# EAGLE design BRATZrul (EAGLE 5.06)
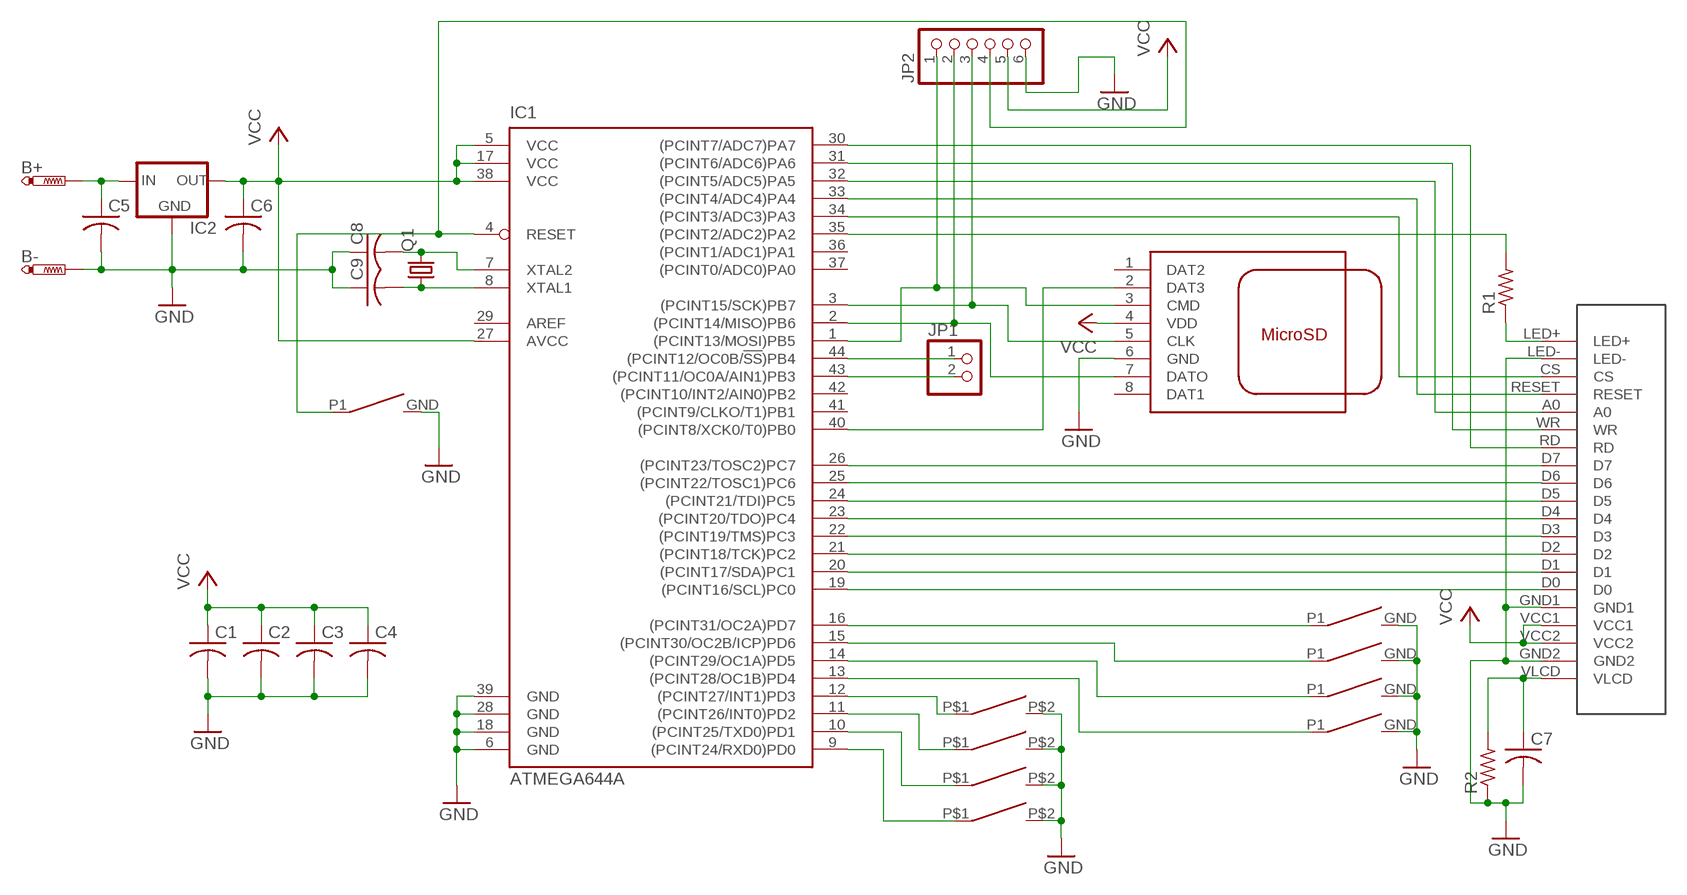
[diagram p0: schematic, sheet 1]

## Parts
B+  PTR1PAD1-13Y  [P1-13Y]
B-  PTR1PAD1-13Y  [P1-13Y]
C1  C-USC0805  [C0805]
C2  C-USC0805  [C0805]
C3  C-USC0805  [C0805]
C4  C-USC0805  [C0805]
C5  C-USC0805  [C0805]
C6  C-USC0805  [C0805]
C7  C-USC0805  [C0805]
C8  C-USC0805  [C0805]
C9  C-USC0805  [C0805]
IC1  ATMEGA644A  [TQFP44]
IC2  XC63FPP  [SOT89R]
JP1  PINHD-1X2  [1X02]
JP2  PINHD-1X6  [1X06]
LCD1  DISPLAY_WOOLWORTH1  [DISPLAYWOOL2]
MIUCHIZ_CURSOR1  MIUCHIZ_CURSOR  [MIUCHIZ_CURSER]
MIUCHIZ_CURSOR2  MIUCHIZ_CURSOR  [MIUCHIZ_CURSER]
MIUCHIZ_CURSOR3  MIUCHIZ_CURSOR  [MIUCHIZ_CURSER]
MIUCHIZ_CURSOR4  MIUCHIZ_CURSOR  [MIUCHIZ_CURSER]
MIUCHIZ_TASTER1  MIUCHIZ_TASTER  [MIUCHIZ_TASTER]
MIUCHIZ_TASTER2  MIUCHIZ_TASTER  [MIUCHIZ_TASTER]
MIUCHIZ_TASTER3  MIUCHIZ_TASTER  [MIUCHIZ_TASTER]
MIUCHIZ_TASTER4  MIUCHIZ_TASTER  [MIUCHIZ_TASTER]
MIUCHIZ_TASTER5  MIUCHIZ_TASTER  [MIUCHIZ_TASTER]
Q1  CRYSTALHC49UP  [HC49UP]
R1  R-US_R0805  [R0805]
R2  R-US_R0805  [R0805]
U$1  112A-TAA0-R01  [112A-TAA0-R01]

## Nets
GND: B-.1(TP) C1.2 C2.2 C3.2 C4.2 C5.2 C6.2 C7.2 C8.1 C9.1 IC1.6(GND) IC1.18(GND) IC1.28(GND) IC1.39(GND) IC2.1(GND) JP2.6 LCD1.GND1 LCD1.GND2 LCD1.LED- MIUCHIZ_CURSOR1.P$2(GND) MIUCHIZ_CURSOR2.P$2(GND) MIUCHIZ_CURSOR3.P$2(GND) MIUCHIZ_CURSOR4.P$2(GND) MIUCHIZ_TASTER1.GND MIUCHIZ_TASTER2.GND MIUCHIZ_TASTER3.GND MIUCHIZ_TASTER4.GND MIUCHIZ_TASTER5.GND R2.1 U$1.6(GND)
N$1: IC1.19((PCINT16/SCL)PC0) LCD1.D0
N$2: IC1.20((PCINT17/SDA)PC1) LCD1.D1
N$3: IC1.21((PCINT18/TCK)PC2) LCD1.D2
N$4: IC1.22((PCINT19/TMS)PC3) LCD1.D3
N$5: IC1.23((PCINT20/TDO)PC4) LCD1.D4
N$6: IC1.24((PCINT21/TDI)PC5) LCD1.D5
N$7: IC1.25((PCINT22/TOSC1)PC6) LCD1.D6
N$8: IC1.26((PCINT23/TOSC2)PC7) LCD1.D7
N$11: IC1.30((PCINT7/ADC7)PA7) LCD1.RD
N$12: IC1.31((PCINT6/ADC6)PA6) LCD1.WR
N$13: IC1.32((PCINT5/ADC5)PA5) LCD1.A0
N$14: IC1.33((PCINT4/ADC4)PA4) LCD1.RESET
N$15: IC1.34((PCINT3/ADC3)PA3) LCD1.CS
N$16: IC1.35((PCINT2/ADC2)PA2) R1.2
N$17: LCD1.LED+ R1.1
N$18: IC1.43((PCINT11/OC0A/AIN1)PB3) JP1.2
N$19: IC1.44((PCINT12/OC0B/!SS!)PB4) JP1.1
N$20: C8.2 IC1.7(XTAL2) Q1.2
N$21: C9.2 IC1.8(XTAL1) Q1.1
N$22: IC1.16((PCINT31/OC2A)PD7) MIUCHIZ_TASTER2.P1
N$23: IC1.15((PCINT30/OC2B/ICP)PD6) MIUCHIZ_TASTER1.P1
N$24: IC1.14((PCINT29/OC1A)PD5) MIUCHIZ_TASTER3.P1
N$25: IC1.13((PCINT28/OC1B)PD4) MIUCHIZ_TASTER4.P1
N$26: IC1.12((PCINT27/INT1)PD3) MIUCHIZ_CURSOR1.P$1(P1)
N$27: IC1.11((PCINT26/INT0)PD2) MIUCHIZ_CURSOR2.P$1(P1)
N$28: IC1.10((PCINT25/TXD0)PD1) MIUCHIZ_CURSOR3.P$1(P1)
N$29: IC1.9((PCINT24/RXD0)PD0) MIUCHIZ_CURSOR4.P$1(P1)
N$30: IC1.3((PCINT15/SCK)PB7) JP2.3 U$1.5(CLK)
N$31: IC1.2((PCINT14/MISO)PB6) JP2.2 U$1.7(DATO)
N$32: IC1.1((PCINT13/MOSI)PB5) JP2.1 U$1.3(CMD)
N$33: IC1.40((PCINT8/XCK0/T0)PB0) U$1.2(DAT3)
N$34: B+.1(TP) C5.1 IC2.2(IN)
N$36: IC1.4(RESET) JP2.4 MIUCHIZ_TASTER5.P1
N$37: C7.1 LCD1.VLCD R2.2
VCC: C1.1 C2.1 C3.1 C4.1 C6.1 IC1.5(VCC) IC1.17(VCC) IC1.27(AVCC) IC1.38(VCC) IC2.3(OUT) JP2.5 LCD1.VCC1 LCD1.VCC2 U$1.4(VDD)
Unconnected: IC1.29(AREF) IC1.36((PCINT1/ADC1)PA1) IC1.37((PCINT0/ADC0)PA0) IC1.41((PCINT9/CLKO/T1)PB1) IC1.42((PCINT10/INT2/AIN0)PB2) U$1.1(DAT2) U$1.8(DAT1)

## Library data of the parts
B+ B- = testpad:PTR1: TEST PIN
C1-C9 = rcl:C-US: CAPACITOR, American symbol
IC1 = atmel:ATMEGA644: 8-bit Microcontroller with 64K Bytes In-System Programmable Flash Source: http://www.atmel.com/dyn/resources/prod_documents/doc2593.pdf
IC2 = v-reg:XC63FP: Positiv Voltage Regulators www.torex.co.jp/english/product/pro02/pdf/0201_xc62fp.pdf
JP1 = pinhead:PINHD-1X2: PIN HEADER
JP2 = pinhead:PINHD-1X6: PIN HEADER
LCD1 = Display_woolworthv2:DISPLAY_WOOLWORTH1
MIUCHIZ_CURSOR1-MIUCHIZ_CURSOR4 = Miuchiz_Taster:MIUCHIZ_CURSOR
MIUCHIZ_TASTER1-MIUCHIZ_TASTER5 = Miuchiz_Taster:MIUCHIZ_TASTER
Q1 = crystal:CRYSTAL: CRYSTAL
R1 R2 = rcl:R-US_: RESISTOR, American symbol
U$1 = con-memcard:112A-TAA0-R01: MicroSD Card Slot Part No.: MICROSD Available at IT-WNS Datasheet : http://www.it-wns.de/data/datenblatt_0000032_1.pdf

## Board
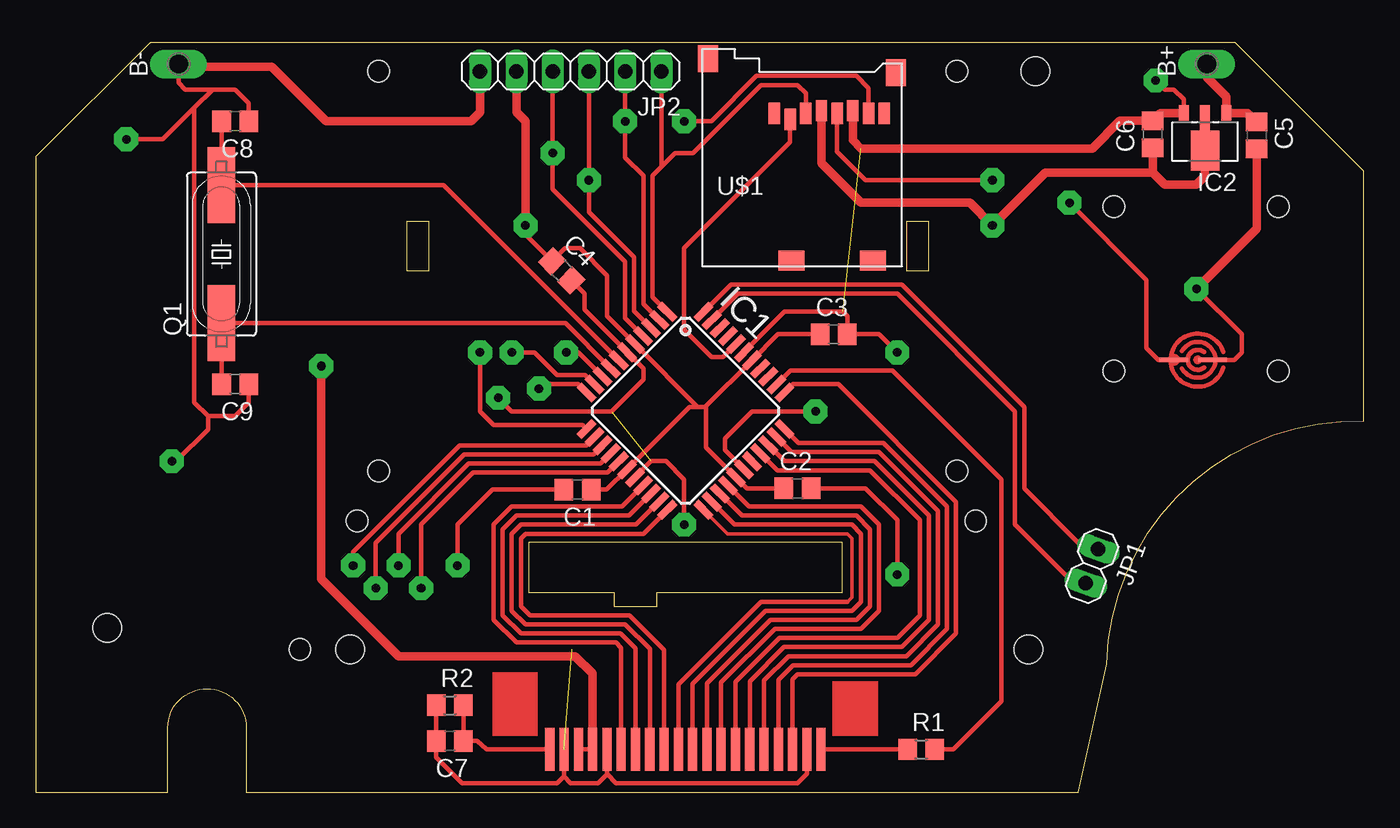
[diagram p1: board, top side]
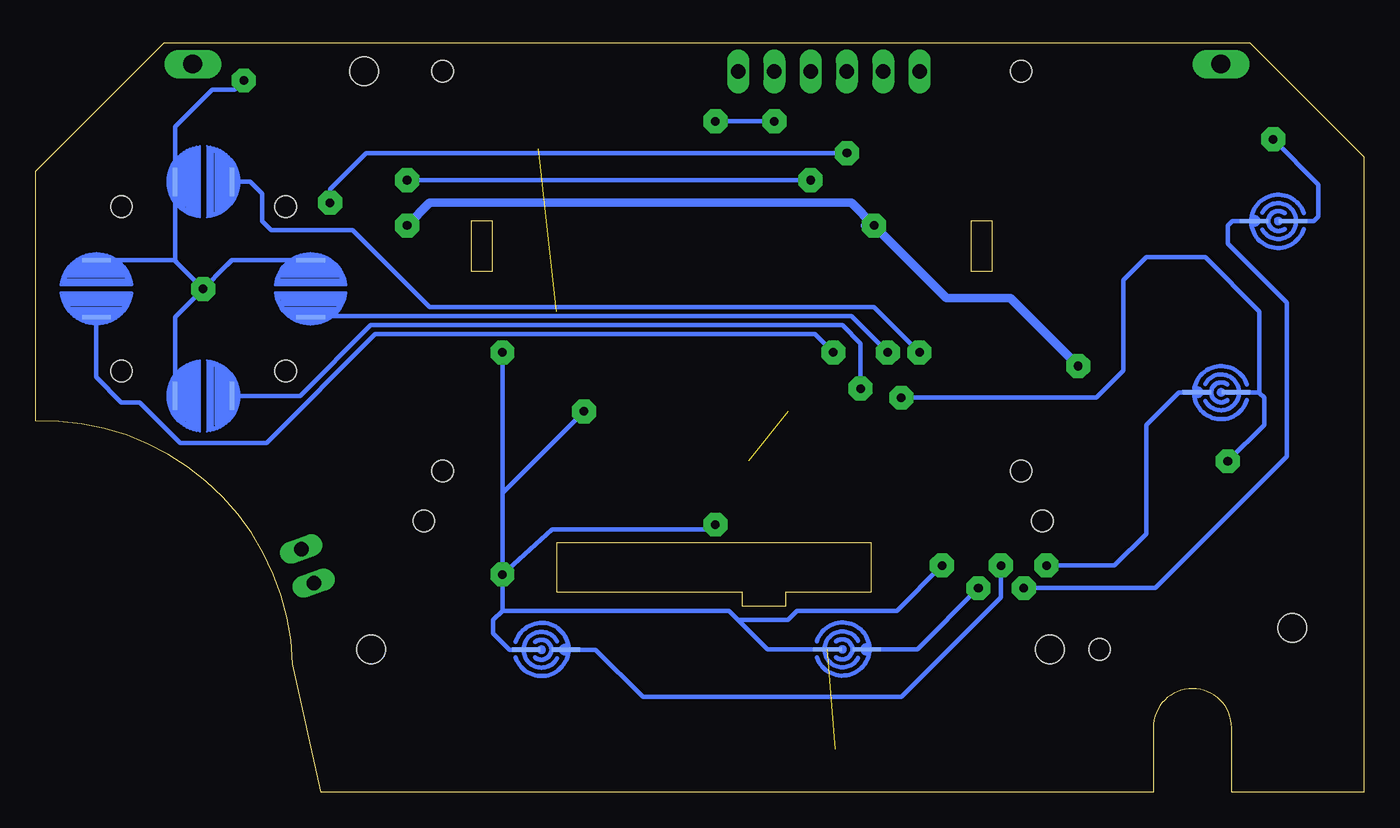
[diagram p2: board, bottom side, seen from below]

Size 93 x 52.5 mm. Coordinates in mm from the lower left corner, seen from the top.
Outline: 0,0 9.25,0 9.25,4.5 arc-180 14.75,4.5 14.75,0 73,0 75,9 arc-90 93,26 93,43.5 84,52.5 8,52.5 0,44.5 0,0
Outline: 34.5,14 40.5,14 40.5,13 43.5,13 43.5,14 56.5,14 56.5,17.5 34.5,17.5 34.5,14
Outline: 26,36.5 26,40 27.5,40 27.5,36.5 26,36.5
Outline: 61,36.5 61,40 62.5,40 62.5,36.5 61,36.5
Copper layers (1*16): Top 0.035mm / dielectric 1.5mm / Bottom 0.035mm
Design rules "default *": minimum track width 10mil, minimum drill 24mil, track to track 8mil, track to pad 8mil, pad to pad 8mil, via to via 8mil, smd to smd 8mil, copper to edge 10mil, drill to drill 8mil, minimum pad ring 10mil, minimum via ring 8mil, stop-mask expansion 4mil, vias tented up to drill 0mil, thermal gap 10mil
Holes 2 mm at 5,11.5 22,10 69.5,10 70,50.5
Holes 1.5 mm at 24,22.5 24,50.5 87,29.5 75.5,29.5 75.5,41 87,41 18.5,10 22.5,19 65.82,19 64.5,50.5 64.5,22.5

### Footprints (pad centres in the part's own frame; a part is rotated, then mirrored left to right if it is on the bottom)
P1-13Y = drill 1.321 pad 1.905 long: 1 0,0
C0805 = smd 1.3 x 1.5: 1 -0.95,0; 2 0.95,0
TQFP44 = smd 1.5 x 0.5: 1 -5.8,4; 2 -5.8,3.2; 3 -5.8,2.4; 4 -5.8,1.6; 5 -5.8,0.8; 6 -5.8,0; 7 -5.8,-0.8; 8 -5.8,-1.6; 9 -5.8,-2.4; 10 -5.8,-3.2; 11 -5.8,-4; 23 5.8,-4; 24 5.8,-3.2; 25 5.8,-2.4; 26 5.8,-1.6; 27 5.8,-0.8; 28 5.8,0; 29 5.8,0.8; 30 5.8,1.6; 31 5.8,2.4; 32 5.8,3.2; 33 5.8,4 | smd 0.5 x 1.5: 12 -4,-5.8; 13 -3.2,-5.8; 14 -2.4,-5.8; 15 -1.6,-5.8; 16 -0.8,-5.8; 17 0,-5.8; 18 0.8,-5.8; 19 1.6,-5.8; 20 2.4,-5.8; 21 3.2,-5.8; 22 4,-5.8; 34 4,5.8; 35 3.2,5.8; 36 2.4,5.8; 37 1.6,5.8; 38 0.8,5.8; 39 0,5.8; 40 -0.8,5.8; 41 -1.6,5.8; 42 -2.4,5.8; 43 -3.2,5.8; 44 -4,5.8
SOT89R = smd 0.7 x 1.1: 1 1.5,-1.75; 2 -1.5,-1.75 | smd 0.7 x 1.8: 3 0,-1.4 | smd 2 x 2.8: 4 0,0.9
1X02 = drill 1.016 long: 1 -1.27,0; 2 1.27,0
1X06 = drill 1.016 long: 1 -6.35,0; 2 -3.81,0; 3 -1.27,0; 4 1.27,0; 5 3.81,0; 6 6.35,0
DISPLAYWOOL2 = smd 3 x 0.635: A0 0,-4; CS 0,-2; D0 0,-14; D1 0,-13; D2 0,-12; D3 0,-11; D4 0,-10; D5 0,-9; D6 0,-8; D7 0,-7; GND1 0,-15; GND2 0,-18; LED+ 0,0; LED- 0,-1; RD 0,-6; RESET 0,-3; VCC1 0,-16; VCC2 0,-17; VLCD 0,-19; WR 0,-5
MIUCHIZ_CURSER = smd 2 x 0.3: P$1 0,-2; P$2 0,2
MIUCHIZ_TASTER = smd 2 x 0.3: GND 1.059,0; P1 -1.691,0
HC49UP = smd 5.334 x 1.93: 1 -4.826,0; 2 4.826,0
R0805 = smd 1.3 x 1.5: 1 -0.95,0; 2 0.95,0
112A-TAA0-R01 = smd 0.8 x 1.5: 1 5.05,10.7; 2 6.15,10.3; 3 7.25,10.7; 4 8.35,10.9; 5 9.45,10.7; 6 10.55,10.9; 7 11.65,10.7; 8 12.75,10.7 | smd 1.4 x 1.9: 9 0.4,14.55; 9@2 13.55,13.55 | smd 1.8 x 1.4: 10 6.25,0.4; 10@2 11.95,0.4

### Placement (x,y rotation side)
B+  82,51 90 top
B-  10,51 90 top
C1  37.94,21.19 180 top
C2  53.34,21.27 0 top
C3  55.88,32.07 0 top
C4  36.83,36.51 315 top
C5  85.5,46 270 top
C6  78.21,46.08 90 top
C7  29,3.59 180 top
C8  13.97,46.99 180 top
C9  13.97,28.57 180 top
IC1  45.5,26.71 315 top
IC2  81.88,45.82 180 top
JP1  73.97,15.83 250 top
JP2  37.47,50.48 180 top
LCD1  55,3 270 top
MIUCHIZ_CURSOR1  81.25,42.75 90 bottom
MIUCHIZ_CURSOR2  81.25,27.75 90 bottom
MIUCHIZ_CURSOR3  73.75,35.25 0 bottom
MIUCHIZ_CURSOR4  88.75,35.25 0 bottom
MIUCHIZ_TASTER1  57.58,9.97 180 bottom
MIUCHIZ_TASTER2  36.5,10 180 bottom
MIUCHIZ_TASTER3  6,40 0 bottom
MIUCHIZ_TASTER4  10,28 0 bottom
MIUCHIZ_TASTER5  81.36,30.28 0 top
Q1  13.01,37.68 90 top
R1  62,3 0 top
R2  29,6.09 0 top
U$1  46.67,36.83 0 top

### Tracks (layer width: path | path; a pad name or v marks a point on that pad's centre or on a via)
GND  (via drill 0.6 pad 1.68)  (3 unrouted)
  Top 0.305: IC1.18 43.1,23.18 44.13,23.18 45.4,21.91 v45.4,18.73 | C1.2 31.99,21.19 29.53,18.73 v29.53,15.88 | v60.33,15.24 60.33,19.05 58.1,21.27 C2.2 | IC1.28 48.26,23.95 48.26,24.77 50.16,26.67 v54.61,26.67 | R2.1 C7.2 28.05,2.43 29.84,0.64 36.51,0.64 37,1.12 LCD1.GND2 37,1.1 37.47,0.64 39.37,0.64 40,1.26 LCD1.GND1 40.01,1.27 40.64,0.64 53.34,0.64 54,1.29 LCD1.LED- | IC1.39 52.45,33.66 56.52,33.66 56.83,33.34 C3.2 59.05,32.07 v60.33,30.8 | B-.1 10,49.69 10.48,49.21 12.38,49.21 | 12.38,49.21 13.97,49.21 14.92,48.26 C8.1 | C9.1 14.92,27.3 13.97,26.35 12.06,26.35 | 12.06,26.35 11.11,27.3 11.11,47.94 | 11.11,47.94 12.38,49.21 | C4.2 38.42,34.92 38.42,33.79 IC1.6 42.55,29.66 42.55,28.89 40.32,26.67 33.34,26.67 v32.38,27.62 | C4.2 | 11.11,47.94 8.89,45.72 v6.35,45.72 | v9.53,23.18 9.84,23.18 12.06,25.4 12.06,26.35 | v78.42,49.85 79.06,49.21 79.69,49.21 80.38,48.52 IC2.1 | MIUCHIZ_TASTER5.GND 83.94,30.28 84.45,30.8 84.45,32.07 v81.28,35.24
  Top 0.61: IC2.1 78.75,47.57 C6.2 75.92,47.02 73.98,45.09 57.78,45.09 57.22,45.65 U$1.6 | JP2.6 31.11,47.62 30.48,46.99 20.32,46.99 16.51,50.8 10.2,50.8 B-.1 | C5.2 85.5,39.46 v81.28,35.24
  Bottom 0.305: 80.96,35.56 80.01,36.51 | 80.01,36.51 79.25,37.27 | MIUCHIZ_CURSOR4.P$2 83.29,37.25 83.03,36.99 | 83.03,36.99 v81.28,35.24 83.25,33.27 MIUCHIZ_CURSOR2.P$2 | MIUCHIZ_CURSOR3.P$2 79.27,37.25 80.01,36.51 | 83.03,36.99 83.25,37.21 MIUCHIZ_CURSOR1.P$2 83.25,46.61 80.64,49.21 79.06,49.21 v78.42,49.85 | MIUCHIZ_TASTER1.GND 59.82,9.97 60.96,11.11 60.96,12.06 60.33,12.7 | 60.33,12.7 44.45,12.7 43.81,12.06 | 43.81,12.06 40.32,12.06 39.69,12.7 32.7,12.7 v29.53,15.88 | MIUCHIZ_TASTER2.GND 41.75,10 43.81,12.06 | v45.4,18.73 45.72,18.41 56.83,18.41 v60.33,15.24 | 60.33,12.7 v60.33,15.24 | 60.33,20.95 v54.61,26.67 | v60.33,15.24 60.33,20.95 | 60.33,20.95 v60.33,30.8 | v6.35,45.72 3.17,42.55 3.17,40.32 3.5,40 MIUCHIZ_TASTER3.GND | MIUCHIZ_TASTER4.GND 7.36,28 7.3,27.94 | 7.3,27.94 6.99,27.62 6.99,25.72 v9.53,23.18 | v32.38,27.62 18.73,27.62 16.83,29.53 16.83,35.88 15.24,37.47 11.11,37.47 7.3,33.66 7.3,27.94
  Bottom 0.61: v81.28,35.24 80.96,35.56
N$1
  Top 0.305: LCD1.D0 41,10.12 40.64,10.48 33.66,10.48 32.07,12.06 32.07,18.73 33.34,20 41.06,20 IC1.19
N$2
  Top 0.305: LCD1.D1 42,10.07 40.96,11.11 33.97,11.11 32.7,12.38 32.7,18.41 33.66,19.37 41.55,19.37 IC1.20
N$3
  Top 0.305: IC1.21 42.05,18.73 33.97,18.73 33.34,18.1 33.34,12.7 34.29,11.75 41.27,11.75 43,10.02 LCD1.D2
N$4
  Top 0.305: IC1.22 42.55,18.1 34.29,18.1 33.97,17.78 33.97,13.02 34.61,12.38 41.59,12.38 44,9.97 LCD1.D3
N$5
  Top 0.254: IC1.23 48.45,18.1 56.83,18.1 57.15,17.78 57.15,13.65 56.83,13.34
  Top 0.305: LCD1.D4 45,7.54 50.8,13.34 56.83,13.34
N$6
  Top 0.305: IC1.24 48.95,18.73 57.15,18.73 57.78,18.1 57.78,13.34 57.15,12.7 51.12,12.7 46,7.58 LCD1.D5
N$7
  Top 0.305: IC1.25 49.45,19.37 57.47,19.37 58.42,18.41 58.42,13.02 57.47,12.06 51.44,12.06 47,7.63 LCD1.D6
N$8
  Top 0.305: IC1.26 49.94,20 57.78,20 59.05,18.73 59.05,12.7 57.78,11.43 51.75,11.43 48,7.68 LCD1.D7
N$11
  Top 0.305: IC1.30 51.93,22.54 58.42,22.54 61.91,19.05 61.91,12.38 60.33,10.79 52.07,10.79 49,7.72 LCD1.RD
N$12
  Top 0.305: IC1.31 52.42,23.18 58.74,23.18 62.55,19.37 62.55,12.06 60.64,10.16 52.39,10.16 50,7.77 LCD1.WR
N$13
  Top 0.305: IC1.32 52.92,23.81 59.05,23.81 63.18,19.68 63.18,11.75 60.96,9.53 52.7,9.53 51,7.82 LCD1.A0
N$14
  Top 0.305: IC1.33 53.42,24.45 59.37,24.45 63.82,20 63.82,11.43 61.28,8.89 53.02,8.89 52,7.87 LCD1.RESET
N$15
  Top 0.305: LCD1.CS 53,7.92 53.34,8.26 61.59,8.26 64.45,11.11 64.45,20.32 56.2,28.57 53.02,28.57 IC1.34
N$16
  Top 0.305: IC1.35 52.85,29.53 60.01,29.53 67.63,21.91 67.63,6.35 64.28,3 R1.2
N$17
  Top 0.305: LCD1.LED+ R1.1
N$18
  Top 0.305: IC1.43 49.19,34.92 60.33,34.92 68.58,26.67 68.58,18.73 72.07,15.24 JP1.2
N$19
  Top 0.305: IC1.44 48.7,35.56 60.64,35.56 69.22,26.99 69.22,21.27 73.03,17.46 JP1.1
N$20
  Top 0.305: IC1.7 28.57,42.5 Q1.2 13.02,42.52 C8.2
N$21
  Top 0.305: IC1.8 37.09,32.85 Q1.1 13.02,32.84 C9.2
N$22  (via drill 0.6 pad 1.68)
  Top 0.305: IC1.16 40.05,22.38 30.64,22.38 26.99,18.73 v26.99,14.29
  Bottom 0.305: v26.99,14.29 31.27,10 MIUCHIZ_TASTER2.P1
N$23  (via drill 0.6 pad 1.68)
  Top 0.305: IC1.15 39.55,23.02 30.32,23.02 25.4,18.1 v25.4,15.88
  Bottom 0.305: MIUCHIZ_TASTER1.P1 53.79,9.97 50.48,6.67 32.38,6.67 25.4,13.65 v25.4,15.88
N$24  (via drill 0.6 pad 1.68)
  Top 0.305: IC1.14 39.05,23.65 30,23.65 23.81,17.46 v23.81,14.29
  Bottom 0.305: v23.81,14.29 14.61,14.29 5.4,23.5 5.4,34.29 9.53,38.42 9.53,39.69 9.21,40 MIUCHIZ_TASTER3.P1
N$25  (via drill 0.6 pad 1.68)
  Top 0.305: IC1.13 38.56,24.29 29.69,24.29 22.23,16.83 v22.23,15.88
  Bottom 0.305: MIUCHIZ_TASTER4.P1 12.96,28 15.24,25.72 15.24,18.1 17.46,15.88 v22.23,15.88
N$26  (via drill 0.6 pad 1.68)
  Top 0.305: IC1.12 38.29,25.72 32.07,25.72 31.11,26.67 v31.11,30.8
  Bottom 0.305: MIUCHIZ_CURSOR1.P$1 77.99,42.75 77.15,41.91 77.15,40.01 76.52,39.37 70.8,39.37 65.41,33.97 34.29,33.97 v31.11,30.8
N$27  (via drill 0.6 pad 1.68)
  Top 0.305: IC1.11 37.98,28.57 35.56,28.57 v35.24,28.26
  Bottom 0.305: MIUCHIZ_CURSOR2.P$1 74.48,27.75 69.53,32.7 36.51,32.7 35.24,31.43 v35.24,28.26
N$28  (via drill 0.6 pad 1.68)
  Top 0.305: IC1.10 38.47,29.21 36.51,29.21 34.92,30.8 v33.34,30.8
  Bottom 0.305: v33.34,30.8 35.88,33.34 73.66,33.34 MIUCHIZ_CURSOR3.P$1
N$29  (via drill 0.6 pad 1.68)
  Top 0.305: IC1.9 38.02,30.8 v37.15,30.8
  Bottom 0.305: MIUCHIZ_CURSOR4.P$1 88.75,29.06 87,27.3 85.72,27.3 82.87,24.45 76.83,24.45 69.22,32.07 38.42,32.07 v37.15,30.8
N$30  (via drill 0.6 pad 1.68)
  Top 0.305: IC1.3 41.91,33.69 41.91,37.47 38.73,40.64 v38.73,42.86 JP2.3 | v66.99,42.86 58.1,42.86 56.12,44.84 U$1.5
  Bottom 0.305: v38.73,42.86 v66.99,42.86
N$31  (via drill 0.6 pad 1.68)
  Top 0.305: IC1.2 42.55,34.19 42.55,43.18 41.27,44.45 41.27,46.04 v41.27,46.99 JP2.2 | U$1.7 58.32,49.31 57.47,50.16 50.48,50.16 47.31,46.99 v45.4,46.99
  Bottom 0.305: v41.27,46.99 v45.4,46.99
N$32
  Top 0.305: IC1.1 43.18,34.68 43.18,43.18 43.81,43.81 | U$1.3 53.92,48.95 53.34,49.53 50.8,49.53 46.04,44.77 44.77,44.77 43.81,43.81 | 43.81,43.81 JP2.1
N$33
  Top 0.305: IC1.40 48.14,30.48 47.31,30.48 45.4,32.38 45.4,38.1 52.82,45.52 U$1.2
N$34
  Top 0.61: B+.1 82,50.08 83.38,48.7 IC2.2 84.88,47.57 C5.1
N$36  (via drill 0.6 pad 1.68)
  Top 0.305: IC1.4 41.27,33.2 41.27,37.15 36.2,42.23 36.2,44.13 v36.2,44.77 JP2.4 | MIUCHIZ_TASTER5.P1 78.62,30.28 77.79,31.11 77.79,35.88 v72.39,41.27
  Bottom 0.305: v72.39,41.27 72.39,42.23 69.85,44.77 v36.2,44.77
N$37
  Top 0.305: R2.2 C7.1 30.89,3.59 31.57,3 LCD1.VLCD
VCC  (via drill 0.6 pad 1.68)
  Top 0.305: 46.35,26.99 IC1.5 40.01,33.34 40.01,36.2 38.1,38.1 37.07,38.1 C4.1 34.29,39.05 v34.29,39.69 | 46.35,26.99 | 46.95,27.03 46.91,26.99 46.35,26.99 | 46.95,27.03 IC1.38 51.99,32.07 C3.1 | 46.95,27.03 46.95,24.12 IC1.27 49.8,21.27 C2.1 | 46.35,26.99 45.78,26.99 IC1.17 39.99,21.19 C1.1 | LCD1.VCC1 LCD1.VCC2
  Top 0.61: IC2.3 81.88,43.15 81.28,42.55 79.06,42.55 78.21,43.39 | 78.21,43.39 C6.1 | LCD1.VCC1 39,8.31 37.78,9.53 25.4,9.53 20,14.92 v20,29.84 | 78.21,43.39 70.7,43.39 v66.99,39.69 65.41,41.27 57.78,41.27 55.88,43.18 | 55.88,43.18 55.56,43.5 | U$1.4 55.02,44.04 55.88,43.18 | v34.29,39.69 34.29,46.99 33.66,47.62 JP2.5
  Bottom 0.61: v34.29,39.69 34.92,39.69 | v66.99,39.69 65.41,41.27 35.88,41.27 v34.29,39.69 | v34.29,39.69 29.21,34.61 24.77,34.61 v20,29.84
